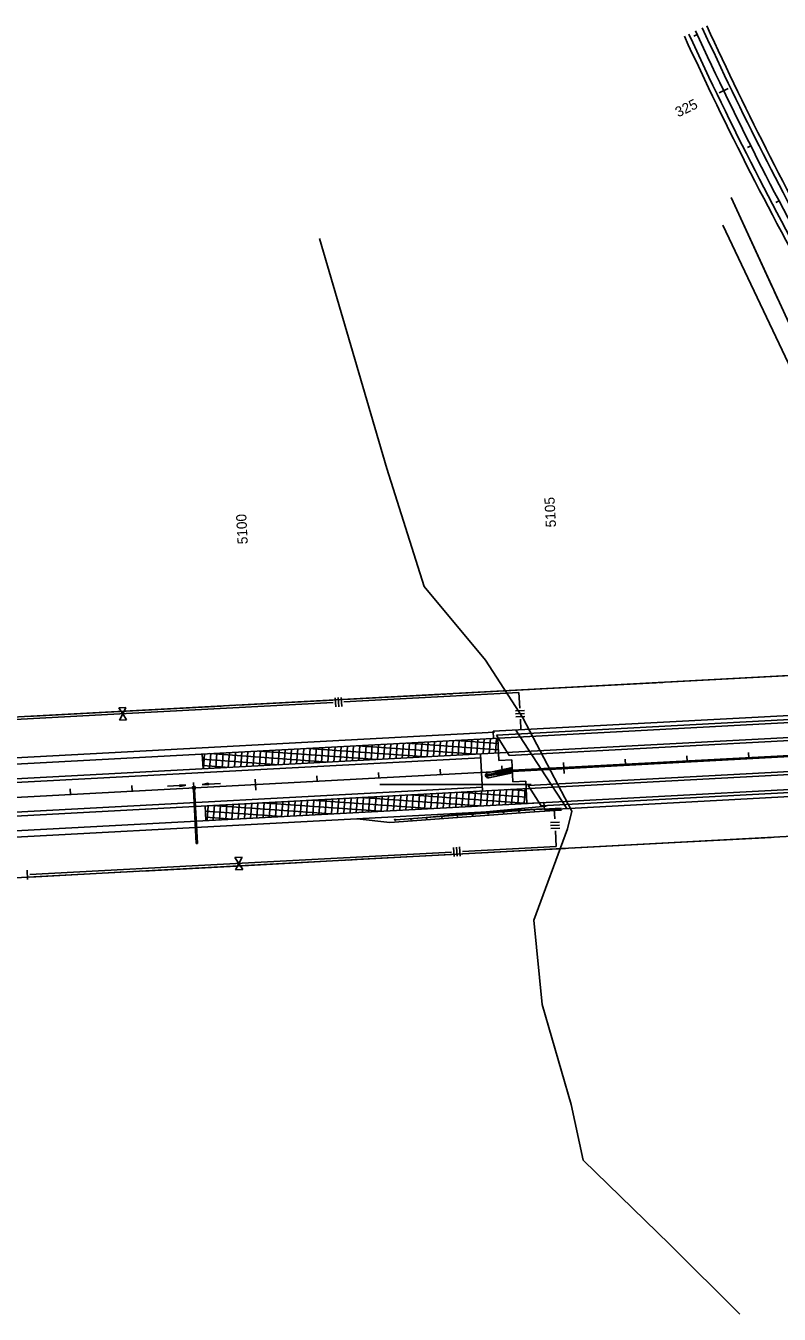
# Model space of a CAD drawing. Extents: x 192699 to 285914, y 194342 to 233219.
# Drawn here: x 254267 to 255487, y 224133 to 226219 of the extents above; entities that cross this region are included whole.
import ezdxf

# ---------------------------------------------------------------- set-up
doc = ezdxf.new("R2010")
doc.units = 0
for name, color, linetype in [('Barrier Wall', 7, 'Continuous'), ('BRIDGE', 7, 'Continuous'), ('CENT LINE', 7, 'Continuous'), ('DRAINAGE', 7, 'Continuous'), ('DRAINAGE ARROWS', 7, 'Continuous'), ('Flood Plain', 7, 'Continuous'), ('GUARDRAIL', 7, 'Continuous'), ('PAVEMENT TRANSITION', 7, 'Continuous'), ('R-W - CofA', 7, 'Continuous'), ('R_Draft', 7, 'Continuous'), ('R_Proposed Guardrail', 7, 'Continuous'), ('R_Water Annot', 7, 'Continuous'), ('ROAD', 7, 'Continuous'), ('SHOULDER', 7, 'Continuous'), ('STATIONING1', 7, 'Continuous'), ('STATIONING2', 7, 'Continuous')]:
    doc.layers.add(name, color=color, linetype=linetype)

msp = doc.modelspace()

# ---------------------------------------------------------------- linework, layer by layer
at = {"layer": 'Barrier Wall'}
for p, q in [((255054.8, 225013.7), (255710.1, 225048.9)), ((255054.9, 225011.8), (255710.2, 225046.9)), ((255013.4, 225010.5), (255013.5, 225008.5))]:
    msp.add_line(p, q, dxfattribs=at)
at = {"layer": 'BRIDGE'}
for p, q in [((255023.9, 225076.8), (255658.5, 225110.8)), ((255029.1, 225070.5), (255663.7, 225104.5)), ((255024.5, 225065.2), (255023.9, 225076.8)), ((255024.5, 225065.2), (255031.2, 225065.6)), ((255031.2, 225065.6), (255033.1, 225029.6)), ((255049.9, 225037.5), (255684.5, 225071.5)), ((255101.7, 225015.3), (255060.4, 225078.7)), ((255033.1, 225029.6), (255053.9, 225030.7)), ((255053.9, 225030.7), (255055.8, 224994.8)), ((255080.5, 224989.1), (255715.1, 225023.1)), ((255101.7, 225015.3), (255143, 224951.8)), ((255055.8, 224994.8), (255076.6, 224995.9)), ((255076.6, 224995.9), (255078.5, 224959.9)), ((255101.4, 224956.2), (255735.9, 224990.2)), ((255106.6, 224949.8), (255741.1, 224983.8)), ((255105.9, 224961.4), (255078.5, 224959.9)), ((255105.9, 224961.4), (255106.6, 224949.8))]:
    msp.add_line(p, q, dxfattribs=at)
for points in [[(255049.9, 225037.5), (255029.1, 225070.5)], [(255101.4, 224956.2), (255080.5, 224989.1)]]:
    msp.add_lwpolyline(points, dxfattribs=at)
at = {"layer": 'CENT LINE'}
msp.add_line((253740.3, 224942.3), (269263.7, 225774), dxfattribs=at)
msp.add_arc((260559.7, 228599.1), 5729.6, 204.63334, 209.53776, dxfattribs=at)
at = {"layer": 'DRAINAGE'}
for p, q in [((254538.2, 224983.1), (254542.9, 224895.2)), ((254540.2, 224983.2), (254544.9, 224895.3))]:
    msp.add_line(p, q, dxfattribs=at)
msp.add_lwpolyline([(254537.2, 224983), (254541.2, 224983.2), (254541, 224987.2), (254537, 224987)], close=True, dxfattribs=at)
msp.add_lwpolyline([(254542.9, 224895.2), (254544.9, 224895.3)], dxfattribs=at)
at = {"layer": 'DRAINAGE ARROWS'}
for p, q in [((254516.1, 224990.3), (254526.2, 224989.3)), ((254516.3, 224987.3), (254516.1, 224990.3)), ((254516.1, 224990), (254524.5, 224989.2)), ((254516.1, 224989.8), (254522.8, 224989.1)), ((254516.1, 224989.5), (254521.1, 224989)), ((254516.2, 224989.2), (254519.4, 224988.9)), ((254516.2, 224987.5), (254524.5, 224989.2)), ((254516.2, 224987.8), (254522.8, 224989.1)), ((254516.2, 224988), (254521.1, 224989)), ((254516.2, 224989), (254517.8, 224988.8)), ((254516.2, 224988.3), (254519.4, 224988.9)), ((254516.2, 224988.5), (254517.8, 224988.8)), ((254516.3, 224987.3), (254526.2, 224989.3)), ((254562.4, 224992.8), (254552.5, 224990.7)), ((254562.5, 224989.8), (254552.5, 224990.7)), ((254562.4, 224992.5), (254554.1, 224990.8)), ((254562.5, 224990), (254554.1, 224990.8)), ((254562.4, 224992.2), (254555.8, 224990.9)), ((254562.5, 224990.3), (254555.8, 224990.9)), ((254562.4, 224992), (254557.5, 224991)), ((254562.5, 224990.5), (254557.5, 224991)), ((254562.4, 224991.7), (254559.2, 224991.1)), ((254562.5, 224990.8), (254559.2, 224991.1)), ((254562.4, 224991.5), (254560.9, 224991.2)), ((254562.4, 224991), (254560.9, 224991.2)), ((254562.5, 224989.8), (254562.4, 224992.8))]:
    msp.add_line(p, q, dxfattribs=at)
at = {"layer": 'Flood Plain'}
for points in [[(255395.7, 225896.3), (255506.8, 225662.2), (255577, 225476.9), (255602.4, 225375.5), (255658.9, 225225.2), (255662.8, 225141.3)], [(255072, 225098.4), (255011.5, 225192.1), (254912.1, 225311.1), (254851.6, 225502.3), (254793.1, 225701.3), (254742.4, 225874.9)], [(255072, 225098.4), (255150.9, 224947.6), (255144.1, 224918.9), (255089.5, 224770.7), (255103.2, 224634.1), (255150, 224472.2), (255169.5, 224382.4), (255309.9, 224245.9), (255423, 224132.7)]]:
    msp.add_lwpolyline(points, dxfattribs=at)
at = {"layer": 'GUARDRAIL'}
for p, q in [((255085.1, 224990.6), (254840.1, 224990.8)), ((255109.4, 224955.6), (254915.2, 224937.2))]:
    msp.add_line(p, q, dxfattribs=at)
at = {"layer": 'PAVEMENT TRANSITION'}
for p, q in [((254957.1, 225037.6), (254958.8, 225061.7)), ((254964.1, 225062), (255031.7, 225057.1)), ((254967.1, 225038.1), (254968.9, 225062.2)), ((254977.2, 225038.6), (254978.9, 225062.8)), ((254987.3, 225039.2), (254989, 225063.3)), ((254997.3, 225039.7), (254999.1, 225063.8)), ((255007.4, 225040.2), (255009.1, 225064.4)), ((255017.5, 225040.8), (255019.2, 225064.9)), ((255027.5, 225041.3), (255029.3, 225065.5)), ((254564.6, 225016.5), (254566.3, 225040.7)), ((254564.8, 225040.6), (254756.2, 225026.8)), ((254574.6, 225017.1), (254576.4, 225041.2)), ((254584.7, 225017.6), (254586.4, 225041.7)), ((254594.7, 225018.1), (254596.5, 225042.3)), ((254604.8, 225018.7), (254606.5, 225042.8)), ((254614.9, 225019.2), (254616.6, 225043.3)), ((254624.9, 225019.8), (254626.7, 225043.9)), ((254635, 225020.3), (254636.7, 225044.4)), ((254644.6, 225044.8), (254836.1, 225031.1)), ((254645.1, 225020.8), (254646.8, 225045)), ((254655.1, 225021.4), (254656.9, 225045.5)), ((254665.2, 225021.9), (254666.9, 225046)), ((254675.3, 225022.5), (254677, 225046.6)), ((254685.3, 225023), (254687.1, 225047.1)), ((254695.4, 225023.5), (254697.1, 225047.7)), ((254705.5, 225024.1), (254707.2, 225048.2)), ((254715.5, 225024.6), (254717.3, 225048.7)), ((254724.5, 225049.1), (254915.9, 225035.3)), ((254725.6, 225025.2), (254727.3, 225049.3)), ((254735.7, 225025.7), (254737.4, 225049.8)), ((254745.7, 225026.2), (254747.5, 225050.4)), ((254755.8, 225026.8), (254757.5, 225050.9)), ((254765.8, 225027.3), (254767.6, 225051.4)), ((254775.9, 225027.8), (254777.6, 225052)), ((254786, 225028.4), (254787.7, 225052.5)), ((254796, 225028.9), (254797.8, 225053.1)), ((254804.4, 225053.4), (254995.8, 225039.6)), ((254806.1, 225029.5), (254807.8, 225053.6)), ((254816.2, 225030), (254817.9, 225054.1)), ((254826.2, 225030.5), (254828, 225054.7)), ((254836.3, 225031.1), (254838, 225055.2)), ((254846.4, 225031.6), (254848.1, 225055.7)), ((254856.4, 225032.2), (254858.2, 225056.3)), ((254866.5, 225032.7), (254868.2, 225056.8)), ((254876.6, 225033.2), (254878.3, 225057.4)), ((254884.2, 225057.7), (255032.2, 225047)), ((254886.6, 225033.8), (254888.4, 225057.9)), ((254896.7, 225034.3), (254898.4, 225058.4)), ((254906.7, 225034.9), (254908.5, 225059)), ((254916.8, 225035.4), (254918.6, 225059.5)), ((254926.9, 225035.9), (254928.6, 225060.1)), ((254936.9, 225036.5), (254938.7, 225060.6)), ((254947, 225037), (254948.7, 225061.1)), ((254552.7, 225039.9), (254554, 225016)), ((254553.1, 225031.4), (254676.4, 225022.5)), ((254553.7, 225021.3), (254596.5, 225018.2)), ((254554.5, 225016), (254556.2, 225040.1)), ((254963.1, 224953.8), (254964.8, 224977.9)), ((254969.1, 224978.1), (255077.9, 224970.3)), ((254973.1, 224954.3), (254974.9, 224978.4)), ((254983.2, 224954.8), (254984.9, 224979)), ((254993.2, 224955.4), (254995, 224979.5)), ((255003.3, 224955.9), (255005, 224980)), ((255013.4, 224956.4), (255015.1, 224980.6)), ((255023.4, 224957), (255025.2, 224981.1)), ((255033.5, 224957.5), (255035.2, 224981.7)), ((255043.6, 224958.1), (255045.3, 224982.2)), ((255048.9, 224982.4), (255077.4, 224980.3)), ((255053.6, 224958.6), (255055.4, 224982.7)), ((255063.7, 224959.1), (255065.4, 224983.3)), ((255073.8, 224959.7), (255075.5, 224983.8)), ((254580.6, 224933.3), (254582.3, 224957.4)), ((254590.7, 224933.8), (254592.4, 224957.9)), ((254600.7, 224934.3), (254602.5, 224958.5)), ((254610.8, 224934.9), (254612.5, 224959)), ((254620.9, 224935.4), (254622.6, 224959.5)), ((254630.9, 224936), (254632.7, 224960.1)), ((254641, 224936.5), (254642.7, 224960.6)), ((254649.7, 224961), (254841.1, 224947.2)), ((254651, 224937), (254652.8, 224961.2)), ((254661.1, 224937.6), (254662.9, 224961.7)), ((254671.2, 224938.1), (254672.9, 224962.2)), ((254681.2, 224938.7), (254683, 224962.8)), ((254691.3, 224939.2), (254693, 224963.3)), ((254701.4, 224939.7), (254703.1, 224963.9)), ((254711.4, 224940.3), (254713.2, 224964.4)), ((254721.5, 224940.8), (254723.2, 224964.9)), ((254729.5, 224965.3), (254921, 224951.5)), ((254731.6, 224941.4), (254733.3, 224965.5)), ((254741.6, 224941.9), (254743.4, 224966)), ((254751.7, 224942.4), (254753.4, 224966.6)), ((254761.8, 224943), (254763.5, 224967.1)), ((254771.8, 224943.5), (254773.6, 224967.6)), ((254781.9, 224944), (254783.6, 224968.2)), ((254792, 224944.6), (254793.7, 224968.7)), ((254802, 224945.1), (254803.8, 224969.3)), ((254809.4, 224969.6), (255000.8, 224955.8)), ((254812.1, 224945.7), (254813.8, 224969.8)), ((254822.1, 224946.2), (254823.9, 224970.3)), ((254832.2, 224946.7), (254834, 224970.9)), ((254842.3, 224947.3), (254844, 224971.4)), ((254852.3, 224947.8), (254854.1, 224971.9)), ((254862.4, 224948.4), (254864.1, 224972.5)), ((254872.5, 224948.9), (254874.2, 224973)), ((254882.5, 224949.4), (254884.3, 224973.6)), ((254889.2, 224973.8), (255080.7, 224960.1)), ((254892.6, 224950), (254894.3, 224974.1)), ((254902.7, 224950.5), (254904.4, 224974.6)), ((254912.7, 224951.1), (254914.5, 224975.2)), ((254922.8, 224951.6), (254924.5, 224975.7)), ((254932.9, 224952.1), (254934.6, 224976.3)), ((254942.9, 224952.7), (254944.7, 224976.8)), ((254953, 224953.2), (254954.7, 224977.3)), ((254557.2, 224956), (254558.5, 224932.1)), ((254557.6, 224947.6), (254681.4, 224938.7)), ((254558.2, 224937.5), (254601.5, 224934.4)), ((254560.5, 224932.2), (254562.2, 224956.3)), ((254569.8, 224956.7), (254761.2, 224942.9)), ((254570.5, 224932.7), (254572.3, 224956.9))]:
    msp.add_line(p, q, dxfattribs=at)
at = {"layer": 'R-W - CofA'}
for p, q in [((255534.4, 225668.3), (255409.4, 225941)), ((254768, 225131), (254768.8, 225116.4)), ((254772.9, 225131.3), (254773.7, 225116.6)), ((254777.8, 225131.5), (254778.6, 225116.9)), ((255065.5, 225139.6), (255066.9, 225114)), ((254417.6, 225114.9), (254429.1, 225115.5)), ((254423.9, 225105.2), (254417.6, 225114.9)), ((254418.7, 225095), (254423.9, 225105.2)), ((254429.1, 225115.5), (254423.9, 225105.2)), ((254423.9, 225105.2), (254430.1, 225095.6)), ((255059.8, 225109.9), (255074.4, 225110.7)), ((255060.1, 225105), (255074.7, 225105.8)), ((254430.1, 225095.6), (254418.7, 225095)), ((255060.3, 225100.1), (255075, 225100.9)), ((255067.8, 225096.6), (255068.8, 225079.2)), ((255123.6, 224934.9), (255122.7, 224950.7)), ((255116.5, 224929), (255131.2, 224929.8)), ((255116.8, 224924.1), (255131.4, 224924.9)), ((255117.1, 224919.2), (255131.7, 224920)), ((255126, 224890.3), (255124.6, 224915.4)), ((254959.6, 224888.8), (254960.4, 224874)), ((254964.5, 224889.1), (254965.3, 224874.3)), ((254969.4, 224889.4), (254970.2, 224874.6)), ((254605.4, 224872.5), (254617, 224873.1)), ((254611.7, 224862.8), (254605.4, 224872.5)), ((254606.5, 224852.4), (254611.7, 224862.8)), ((254618.1, 224853), (254606.5, 224852.4)), ((254617, 224873.1), (254611.7, 224862.8)), ((254611.7, 224862.8), (254618.1, 224853)), ((254268.9, 224851.8), (254269.7, 224837))]:
    msp.add_line(p, q, dxfattribs=at)
for points in [[(255476.1, 225795.5), (255409.4, 225941)], [(255480.6, 225785.6), (255478.1, 225791)], [(255485.2, 225775.7), (255482.7, 225781.1)], [(253912.1, 225081.7), (255693.6, 225177.2)], [(255475, 225165.4), (255629, 225173.7)], [(254962.7, 225138), (255122.5, 225146.6)], [(255122.5, 225146.6), (255276.6, 225154.8)], [(255281.5, 225155.1), (255287.5, 225155.4)], [(255292.4, 225155.7), (255298.4, 225156)], [(255303.3, 225156.2), (255475, 225165.4)], [(254610.2, 225119.1), (254764.3, 225127.4)], [(254781.9, 225128.3), (254935.9, 225136.6)], [(254782.1, 225124.4), (255065.5, 225139.6)], [(254940.9, 225136.8), (254946.8, 225137.1)], [(254951.8, 225137.4), (254957.7, 225137.7)], [(254089, 225087.3), (254429.6, 225105.5)], [(254269.6, 225100.9), (254429.4, 225109.4)], [(254429.4, 225109.4), (254583.5, 225117.7)], [(254429.6, 225105.5), (254764.5, 225123.5)], [(254588.4, 225117.9), (254594.4, 225118.3)], [(254599.3, 225118.5), (254605.3, 225118.9)], [(253917.2, 224821.6), (255810.1, 224923)], [(255156.8, 224888), (255318.3, 224896.7)], [(255318.3, 224896.7), (255474, 224905)], [(255479, 224905.3), (255485.1, 224905.6)], [(254617.5, 224863.1), (254956, 224881.2)], [(254800.5, 224868.9), (254956.3, 224877.3)], [(254973.8, 224882.2), (255126, 224890.3)], [(254974, 224878.2), (255129.7, 224886.6)], [(255134.7, 224886.8), (255140.7, 224887.2)], [(255145.8, 224887.4), (255151.8, 224887.8)], [(254273.2, 224844.6), (254617.5, 224863.1)], [(254456.2, 224850.5), (254617.8, 224859.1)], [(254617.8, 224859.1), (254773.5, 224867.5)], [(254778.5, 224867.8), (254784.5, 224868.1)], [(254789.5, 224868.3), (254795.5, 224868.7)], [(254273.4, 224840.7), (254429.2, 224849)], [(254434.2, 224849.3), (254440.2, 224849.6)], [(254445.2, 224849.9), (254451.2, 224850.2)]]:
    msp.add_lwpolyline(points, dxfattribs=at)
at = {"layer": 'R_Draft'}
for p, q in [((255014.8, 225009.6), (255052.3, 225017.6)), ((255016.6, 225001.3), (255055, 225009.5)), ((255055, 225009.5), (255054.7, 225015.7))]:
    msp.add_line(p, q, dxfattribs=at)
for centre in [(255014.2, 225005.1), (255017.6, 225005.9), (255021, 225006.6), (255024.5, 225007.3), (255027.9, 225008.1), (255030.9, 225010.6), (255031.7, 225007), (255034.4, 225011.4), (255035.1, 225007.7), (255037.8, 225012.1), (255038.6, 225008.4), (255041.2, 225012.8), (255042, 225009.2), (255044.7, 225013.6), (255045.4, 225009.9), (255048.1, 225014.3), (255048.9, 225010.6), (255051.5, 225015), (255052.3, 225011.4)]:
    msp.add_circle(centre, 1.38, dxfattribs=at)
for centre, radius, start, end in [((255015.7, 225005.5), 4.25, 102.0481, 282.0481), ((255052.7, 225015.7), 2, 2.5857, 102.0481)]:
    msp.add_arc(centre, radius, start, end, dxfattribs=at)
at = {"layer": 'R_Proposed Guardrail'}
for p, q in [((254965.9, 224937.2), (254856.2, 224929.2)), ((254915.8, 224937.1), (254865.9, 224933.4)), ((255090.4, 224949.9), (254915.8, 224937.1)), ((255090.6, 224946.4), (254965.9, 224937.2)), ((255115.3, 224951.2), (255090.4, 224949.9)), ((255115.5, 224947.8), (255090.5, 224946.4)), ((255115.3, 224951.2), (255134, 224952.3)), ((255115.5, 224947.8), (255134.2, 224948.8)), ((254856.2, 224929.2), (254803.6, 224935)), ((254864.1, 224934.2), (254865.9, 224933.4)), ((254864.1, 224934.2), (254864.3, 224932.3)), ((254864.3, 224932.3), (254865.9, 224933.4))]:
    msp.add_line(p, q, dxfattribs=at)
for centre in [(254915.8, 224936.3), (254940.8, 224938.1), (254965.7, 224940), (254990.6, 224941.8), (255015.6, 224943.7), (255040.5, 224945.5), (255065.4, 224947.3), (255090.4, 224949.2), (255109.1, 224950.2), (255115.4, 224950.5), (255118.5, 224950.7), (255121.6, 224950.8), (255124.7, 224951), (255126.3, 224951.1), (255127.8, 224951.2), (255129.4, 224951.3), (255131, 224951.3), (255132.5, 224951.4), (254890.9, 224934.5)]:
    msp.add_circle(centre, 0.75, dxfattribs=at)
at = {"layer": 'R_Water Annot'}
for p, q in [((254496.2, 224987.7), (254526.2, 224989.3)), ((254516.1, 224990.3), (254526.2, 224989.3)), ((254516.3, 224987.3), (254516.1, 224990.3)), ((254516.1, 224990), (254524.5, 224989.2)), ((254516.1, 224989.8), (254522.8, 224989.1)), ((254516.1, 224989.5), (254521.1, 224989)), ((254516.2, 224989.2), (254519.4, 224988.9)), ((254516.2, 224987.5), (254524.5, 224989.2)), ((254516.2, 224987.8), (254522.8, 224989.1)), ((254516.2, 224988), (254521.1, 224989)), ((254516.2, 224989), (254517.8, 224988.8)), ((254516.2, 224988.3), (254519.4, 224988.9)), ((254516.2, 224988.5), (254517.8, 224988.8)), ((254516.3, 224987.3), (254526.2, 224989.3)), ((254562.4, 224992.8), (254552.5, 224990.7)), ((254582.4, 224992.4), (254552.5, 224990.7)), ((254562.5, 224989.8), (254552.5, 224990.7)), ((254562.4, 224992.5), (254554.1, 224990.8)), ((254562.5, 224990), (254554.1, 224990.8)), ((254562.4, 224992.2), (254555.8, 224990.9)), ((254562.5, 224990.3), (254555.8, 224990.9)), ((254562.4, 224992), (254557.5, 224991)), ((254562.5, 224990.5), (254557.5, 224991)), ((254562.4, 224991.7), (254559.2, 224991.1)), ((254562.5, 224990.8), (254559.2, 224991.1)), ((254562.4, 224991.5), (254560.9, 224991.2)), ((254562.4, 224991), (254560.9, 224991.2)), ((254562.5, 224989.8), (254562.4, 224992.8))]:
    msp.add_line(p, q, dxfattribs=at)
at = {"layer": 'ROAD'}
for p, q in [((255085.2, 225044.4), (265536.9, 225604.4)), ((255121.9, 224986.3), (265503.9, 225542.5)), ((250995.3, 224849.3), (255646.7, 225098.5)), ((250996.6, 224825.4), (255085.2, 225044.4)), ((255003.3, 225040), (255006.5, 224980.1)), ((251001.1, 224741.5), (256101.5, 225014.7)), ((250999.8, 224765.5), (255121.9, 224986.3))]:
    msp.add_line(p, q, dxfattribs=at)
for radius, start, end in [(5717.6, 204.6333, 209.1722), (5741.6, 204.63334, 209.53776)]:
    msp.add_arc((260559.7, 228599.1), radius, start, end, dxfattribs=at)
at = {"layer": 'SHOULDER'}
for p, q in [((250994.8, 224859.3), (255026.1, 225075.3)), ((250996.9, 224819.4), (255003.7, 225034)), ((250999.5, 224771.4), (255006.2, 224986.1)), ((251001.6, 224731.5), (255104.4, 224951.3))]:
    msp.add_line(p, q, dxfattribs=at)
for radius, start, end in [(5709.6, 204.6333, 209.3673), (5749.6, 204.63334, 209.53776)]:
    msp.add_arc((260559.7, 228599.1), radius, start, end, dxfattribs=at)
at = {"layer": 'STATIONING1'}
for points in [[(255437.4, 225042.3), (255437.8, 225033.3)], [(255037.9, 225020.9), (255038.4, 225011.9)], [(255137.8, 225026.2), (255138.8, 225008.2)], [(255237.6, 225031.6), (255238.1, 225022.6)], [(255337.5, 225036.9), (255338, 225027.9)], [(254638.5, 224999.5), (254639.5, 224981.5)], [(254738.4, 225004.8), (254738.8, 224995.8)], [(254838.2, 225010.2), (254838.7, 225001.2)], [(254938.1, 225015.5), (254938.6, 225006.5)], [(254338.9, 224983.4), (254339.4, 224974.4)], [(254438.8, 224988.8), (254439.3, 224979.8)], [(254538.6, 224994.1), (254539.1, 224985.1)]]:
    msp.add_lwpolyline(points, dxfattribs=at)
at = {"layer": 'STATIONING2'}
for points in [[(255348.9, 226202.5), (255354.3, 226205)], [(255389.7, 226111), (255404.1, 226118)], [(255435.7, 226022.1), (255441, 226024.8)], [(255481.4, 225933.1), (255486.7, 225935.8)]]:
    msp.add_lwpolyline(points, dxfattribs=at)

# ---------------------------------------------------------------- texts
at = {"layer": 'STATIONING1'}
for s, p in [('5105', (255125.6, 225407.5)), ('5100', (254626.4, 225380.1))]:
    msp.add_text(s, height=16.5, rotation=93.0667, dxfattribs=at).set_placement(p)
at = {"layer": 'STATIONING2'}
msp.add_text('325', height=16.5, rotation=25.6995, dxfattribs=at).set_placement((255323.4, 226070.8))

doc.saveas('drawing.dxf')
